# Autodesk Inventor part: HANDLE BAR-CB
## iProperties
Created: 2006-07
Part Number: HANDLE BAR-CB
Material: Steel
Document SubType Name: Modeling
Designer: rollin42
Mass: 53.2788 g
Surface Area: 29.9274 cm^2
Volume: 6.78711 cm^3
Density: 7.85 g/cm^3
Stock Number: HANDLE BAR-CB
Author: rollin42
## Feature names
1. Extrusion1
